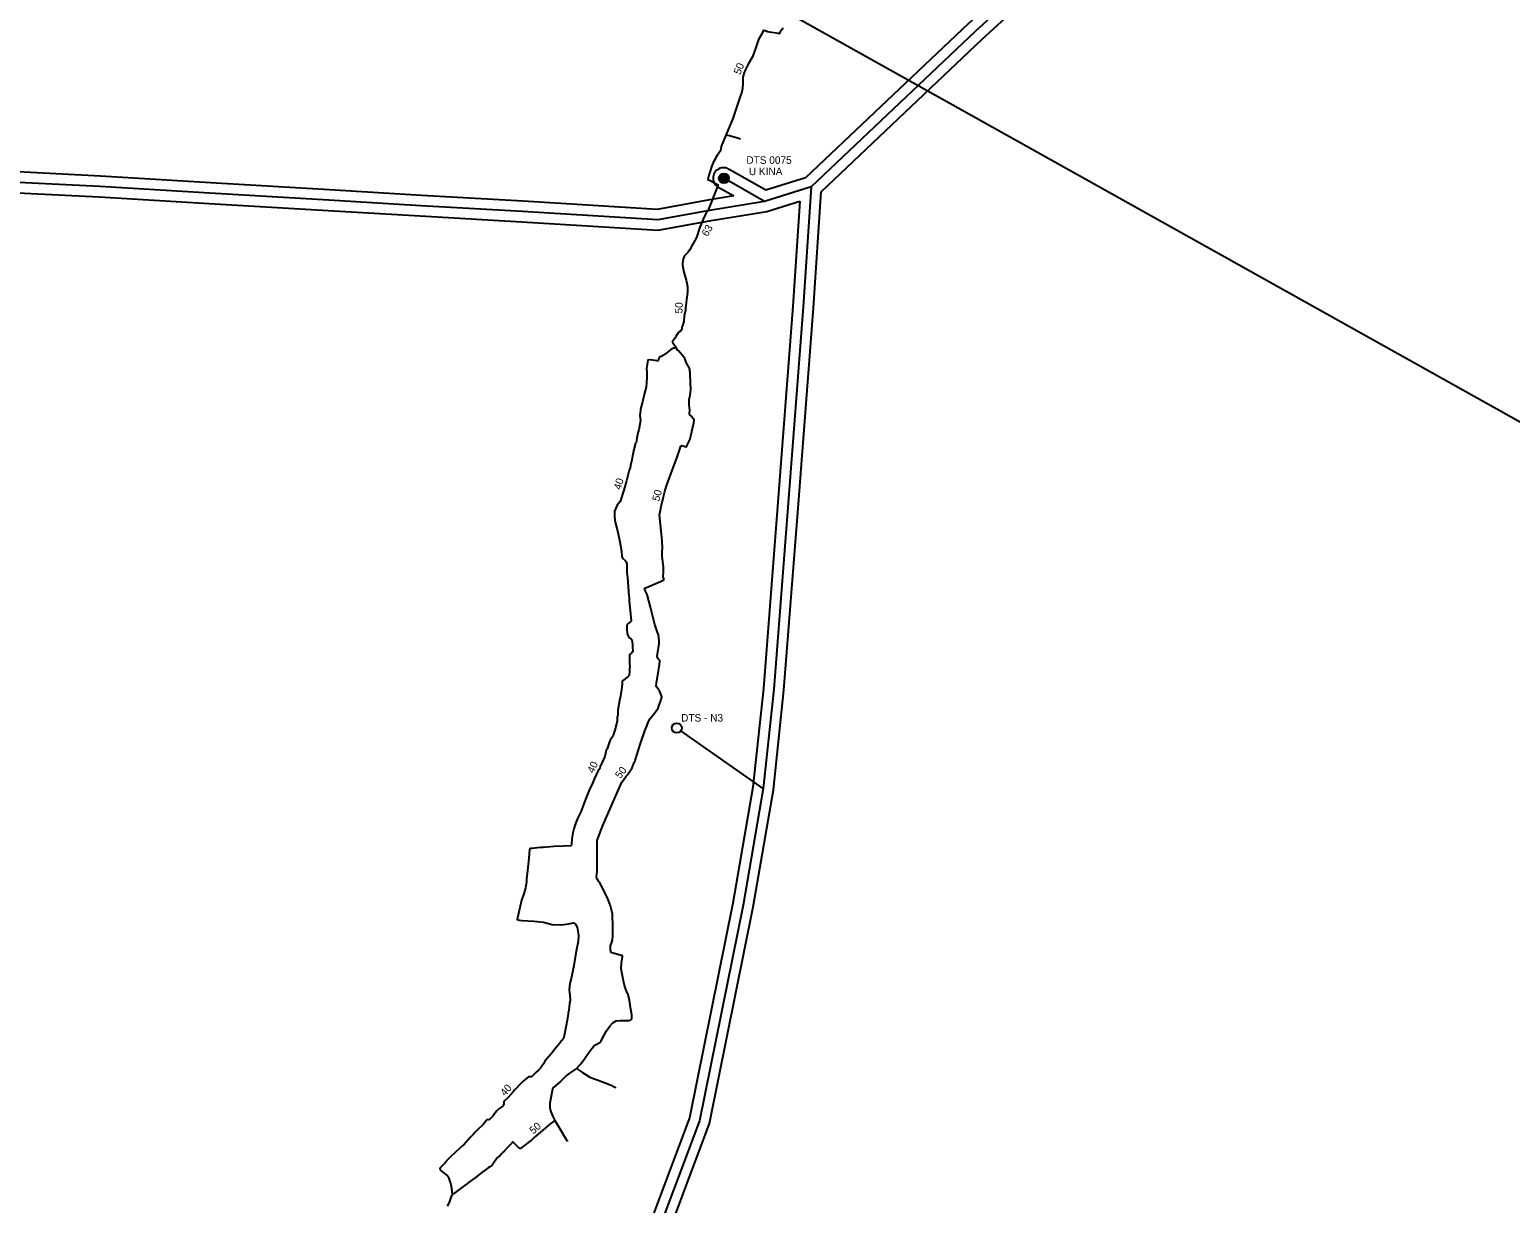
# Model space of a CAD drawing. Extents: x -545241 to -532622, y -1042837 to -1037240.
# Drawn here: x -544227 to -542654, y -1041842 to -1040596 of the extents above; entities that cross this region are included whole.
import ezdxf

# ---------------------------------------------------------------- set-up
doc = ezdxf.new("R2010")
doc.units = 0
for name, color, linetype in [('Vrstva 11', 7, 'Continuous'), ('Vrstva 12', 7, 'Continuous'), ('Vrstva 16', 7, 'Continuous'), ('Vrstva 18', 7, 'Continuous'), ('Vrstva 29', 7, 'Continuous'), ('Vrstva 33', 7, 'Continuous'), ('Vrstva 38', 7, 'Continuous'), ('Vrstva 59', 7, 'Continuous'), ('Vrstva 6', 7, 'Continuous')]:
    doc.layers.add(name, color=color, linetype=linetype)

# ---------------------------------------------------------------- blocks, each defined once
blk = doc.blocks.new('ETRAFN')
at = {"layer": 'Vrstva 6'}
blk.add_circle((0, 0), 7.5, dxfattribs=at)

msp = doc.modelspace()

# ---------------------------------------------------------------- linework, layer by layer
at = {"layer": 'Vrstva 11'}
msp.add_line((-543448.1, -1041401.7), (-543535.6, -1041340.6), dxfattribs=at)
at = {"layer": 'Vrstva 12'}
for radius in [5.25, 4.55, 3.85, 3.15, 2.45, 1.75, 1.05, 0.35]:
    msp.add_circle((-543489.8, -1040753.7), radius, dxfattribs=at)
at = {"layer": 'Vrstva 18'}
for points in [[(-543426.9, -1040594.3), (-543429.9, -1040598), (-543431.1, -1040600.2), (-543431.8, -1040599.9), (-543431.9, -1040600), (-543441.2, -1040598.4), (-543443.1, -1040598.1), (-543443.1, -1040598.1), (-543443.3, -1040597.9), (-543444.6, -1040597.6), (-543445.9, -1040597.2), (-543447.6, -1040596.7), (-543447.8, -1040596.7), (-543448, -1040596.8), (-543448.1, -1040597.2), (-543449.8, -1040600.8), (-543452.9, -1040606.2), (-543455, -1040612.6), (-543456.6, -1040616.9), (-543459.2, -1040624.7), (-543463.8, -1040632.5), (-543466.4, -1040637.5), (-543466.7, -1040638), (-543468.4, -1040642.4), (-543469.6, -1040646.4), (-543469.7, -1040653), (-543470, -1040658.2), (-543471.2, -1040663.4)], [(-543471.2, -1040663.4), (-543472, -1040665.8), (-543480.3, -1040690.3), (-543486.8, -1040705.4), (-543487.8, -1040707.9), (-543492.5, -1040719.9), (-543493.4, -1040724.5), (-543496.8, -1040729.5), (-543498.8, -1040732.4), (-543499.2, -1040733.2), (-543501.2, -1040736.8), (-543502.7, -1040740.5), (-543504.2, -1040746.2), (-543505.9, -1040750.5), (-543506.9, -1040755), (-543504.5, -1040756), (-543504.5, -1040756), (-543497.9, -1040759.5), (-543496.4, -1040760.2), (-543495.8, -1040760.6), (-543506.8, -1040788.1), (-543509.2, -1040791.7), (-543511.6, -1040797.1), (-543514, -1040802.5), (-543515.3, -1040805.6), (-543518.9, -1040816.5), (-543524.3, -1040826.1), (-543526.2, -1040830), (-543528, -1040832.5), (-543531.6, -1040836), (-543532.4, -1040837.4), (-543533.1, -1040839.4), (-543533.8, -1040843.9), (-543533.9, -1040846), (-543532.2, -1040853.5), (-543530, -1040861.9), (-543529.3, -1040865.1), (-543528.5, -1040868.8), (-543528.3, -1040871.6), (-543528.5, -1040873.5), (-543528.8, -1040878), (-543529.4, -1040881.9), (-543529.7, -1040886.1), (-543530.6, -1040891.4), (-543530.7, -1040893.9), (-543531.6, -1040897.7), (-543531.9, -1040900.7), (-543532.2, -1040904.9), (-543532.3, -1040905.8), (-543532.5, -1040906.7), (-543533.8, -1040910.4), (-543534.6, -1040911.8), (-543534.6, -1040912.3), (-543534.4, -1040913.4), (-543534.4, -1040914.3), (-543535.8, -1040915.9), (-543537.6, -1040917), (-543537.6, -1040917), (-543538.5, -1040917.8), (-543540.7, -1040921.6), (-543541.6, -1040923.1), (-543542.3, -1040924.2), (-543543.4, -1040925.6), (-543544.4, -1040926.9), (-543544.6, -1040927.3), (-543544.4, -1040927.8), (-543543.8, -1040928.8), (-543540.5, -1040933.3)], [(-543472.1, -1040712), (-543473.2, -1040711.8), (-543475.2, -1040711.2), (-543481.2, -1040709.2), (-543483.8, -1040708.4), (-543487.8, -1040707.9)], [(-543540.5, -1040933.3), (-543542.1, -1040934.1), (-543543.2, -1040934.1), (-543546.3, -1040936), (-543550.1, -1040938.7), (-543554.7, -1040941.9), (-543556.3, -1040942.8), (-543557.7, -1040943.4), (-543558.6, -1040944.2), (-543559.2, -1040945.8), (-543559.3, -1040946), (-543559.7, -1040947.5), (-543560.7, -1040947.6), (-543568.1, -1040946.3), (-543568.4, -1040946.3), (-543570.4, -1040946.7), (-543571.4, -1040951.4), (-543571.8, -1040955.6), (-543571.6, -1040959.6), (-543571.6, -1040965.6), (-543572.5, -1040975.5), (-543574.6, -1040983.3), (-543576.2, -1040990.9), (-543578.3, -1040999), (-543578.4, -1041000), (-543579, -1041005.7), (-543578.5, -1041011), (-543578.9, -1041014.8), (-543580.2, -1041020.7), (-543580.6, -1041022), (-543580.7, -1041022.9), (-543582.4, -1041029.4), (-543582.5, -1041032), (-543582.6, -1041032.9), (-543582.9, -1041034.1), (-543583.5, -1041035), (-543585.6, -1041041.6), (-543586.6, -1041047.1), (-543587.7, -1041052.8), (-543588.8, -1041058.5), (-543588.9, -1041058.7), (-543589.4, -1041061.1), (-543590.4, -1041063.7), (-543593.3, -1041074.9), (-543596.1, -1041084.7), (-543599.5, -1041096), (-543599.8, -1041096.9), (-543603, -1041100.7), (-543605.9, -1041107.3), (-543605.8, -1041113.6), (-543605.3, -1041118.8), (-543602.8, -1041128), (-543602.3, -1041129.9), (-543601.9, -1041131.3), (-543600.2, -1041139.6), (-543598.7, -1041149.7), (-543598.2, -1041155.3), (-543597.3, -1041157.2), (-543594.4, -1041159.9), (-543593.4, -1041161.1), (-543593, -1041163.5), (-543592.9, -1041172.2), (-543592.2, -1041178), (-543591.4, -1041187.1), (-543591.1, -1041192.3), (-543591.1, -1041193), (-543590.5, -1041199.7), (-543590.4, -1041202.7), (-543589.1, -1041216.1), (-543588.4, -1041223.8), (-543588.8, -1041224.7), (-543589.7, -1041225.3), (-543590.5, -1041225.9), (-543591.5, -1041226.4), (-543592.6, -1041227.6), (-543592.9, -1041228.9), (-543592.7, -1041232.7), (-543592.4, -1041237.1), (-543592.2, -1041238.2), (-543591.5, -1041239.7), (-543590, -1041241.7), (-543588.2, -1041243.2), (-543587.6, -1041243.8), (-543587, -1041248.8), (-543586.8, -1041250.7), (-543586.5, -1041256.4), (-543586.6, -1041256.4), (-543586.7, -1041256.7), (-543588, -1041257.8), (-543589.9, -1041259.4), (-543590.2, -1041259.9), (-543590.2, -1041260.6), (-543590.2, -1041262.4), (-543590.1, -1041262.9), (-543590.1, -1041266.3), (-543590, -1041267), (-543590, -1041269), (-543589.7, -1041272.8), (-543589.7, -1041273.2), (-543589.9, -1041273.7), (-543590.2, -1041277.2)], [(-543558.4, -1041245), (-543559.3, -1041238.6), (-543560.5, -1041234.9), (-543563, -1041227.5), (-543564.7, -1041221.8), (-543567.8, -1041209.2), (-543571.4, -1041195.7), (-543573, -1041192.1), (-543574, -1041189.2), (-543573.3, -1041188.7), (-543572.1, -1041188.3), (-543557.2, -1041181.8), (-543553.7, -1041180.2), (-543553.5, -1041179.5), (-543553.7, -1041178.7), (-543554.3, -1041176.8), (-543553.8, -1041171.2), (-543553.8, -1041170), (-543554, -1041166.2), (-543555, -1041157.6), (-543555.3, -1041154.9), (-543555.5, -1041153.8), (-543555.4, -1041150.9), (-543555.3, -1041150.2), (-543555.3, -1041149.6), (-543554.8, -1041146.8), (-543555.4, -1041138.7), (-543556.1, -1041131.6), (-543558, -1041111.1), (-543556.8, -1041104.2), (-543556.3, -1041102.2), (-543554.2, -1041093.3), (-543552.4, -1041086.3), (-543550.6, -1041080.3), (-543550.6, -1041080.1), (-543549.7, -1041077.4), (-543549, -1041075.3), (-543548, -1041072.5), (-543543.6, -1041061), (-543539, -1041048.7), (-543535.5, -1041038.2), (-543535.3, -1041037.6), (-543534.9, -1041037.5), (-543534.9, -1041037.5), (-543532.1, -1041038.3), (-543532, -1041038.3), (-543531.6, -1041038.4), (-543529.8, -1041038.9), (-543529.2, -1041037.8), (-543525.9, -1041031.4), (-543524.6, -1041025.9), (-543523.1, -1041019.3), (-543521.7, -1041013.4), (-543521.7, -1041013.4), (-543521.7, -1041013), (-543521.4, -1041010.9), (-543521.3, -1041010.3), (-543522.6, -1041008.5), (-543523.6, -1041007.1), (-543523.6, -1041007), (-543526.3, -1041004.5), (-543526.3, -1041003.9), (-543526, -1041000), (-543526, -1041000), (-543526.6, -1040994.3), (-543526.6, -1040993.5), (-543526.6, -1040988.4), (-543525.7, -1040983.8), (-543525.1, -1040981.2), (-543524.9, -1040978.3), (-543525.1, -1040970.1), (-543525.7, -1040962), (-543525.7, -1040961.8), (-543525.7, -1040959.7), (-543525.8, -1040958.7), (-543525.8, -1040956.6), (-543527.1, -1040953.9), (-543527.8, -1040953.2), (-543528.9, -1040951.1), (-543529.1, -1040950.8), (-543530.8, -1040946.2), (-543531.4, -1040945.2), (-543532, -1040943.9), (-543537.9, -1040936.9), (-543538.2, -1040936.6), (-543539.1, -1040936.2), (-543539.5, -1040936.1), (-543539.7, -1040935.7), (-543539.9, -1040934.5), (-543540.2, -1040933.7), (-543540.5, -1040933.3)], [(-543646.3, -1041699.1), (-543644.2, -1041696.9), (-543644.1, -1041696.6), (-543642.5, -1041694.7), (-543638.6, -1041689.9), (-543633.1, -1041682), (-543630.1, -1041677.8), (-543628, -1041675.2), (-543626.2, -1041674), (-543621.7, -1041671.5), (-543620.2, -1041669.7), (-543616.5, -1041663), (-543614.3, -1041659.1), (-543612.7, -1041656.5), (-543612.6, -1041656.4), (-543611, -1041654.2), (-543607.7, -1041650.4), (-543604.2, -1041648.5), (-543599.7, -1041647.9), (-543590.9, -1041648.2), (-543589.1, -1041647.6), (-543587.7, -1041646.2), (-543587.4, -1041644.6), (-543587.7, -1041642), (-543589, -1041634.3), (-543589.8, -1041628.8), (-543590.4, -1041625.2), (-543591.6, -1041620.4), (-543592.1, -1041619.2), (-543594.3, -1041614.1), (-543595.8, -1041609.5), (-543597.5, -1041600.7), (-543598.8, -1041593.3), (-543598.6, -1041587), (-543597.3, -1041580.6), (-543597.4, -1041579.7), (-543597.6, -1041579.5), (-543608.7, -1041576.1), (-543609.5, -1041575.8), (-543609.9, -1041575.3), (-543610.3, -1041571.7), (-543610.3, -1041569.6), (-543610.1, -1041568.7), (-543608.8, -1041564.9), (-543608.1, -1041562.3), (-543607.8, -1041558), (-543607.7, -1041551), (-543607.7, -1041548.4), (-543608, -1041535), (-543608.3, -1041533.4), (-543610.2, -1041526.2), (-543613.4, -1041517.9), (-543622, -1041501.3), (-543622.9, -1041500), (-543624.8, -1041497.2), (-543625.2, -1041495), (-543624.3, -1041490), (-543624.3, -1041475.7), (-543624.5, -1041457.7), (-543624.4, -1041457), (-543620.9, -1041447.3), (-543618.2, -1041441), (-543602.5, -1041404.5), (-543598.2, -1041395.1), (-543598.2, -1041395.1), (-543597.9, -1041394.5), (-543593.5, -1041388.6), (-543592, -1041387.3), (-543591, -1041386.2), (-543590.9, -1041385.2), (-543590.7, -1041384.9), (-543587.1, -1041379.6), (-543584.9, -1041374.2), (-543584.4, -1041373.5), (-543584.1, -1041371.8), (-543578.7, -1041354.9), (-543573.8, -1041340.4), (-543571.1, -1041334.5), (-543569.8, -1041330.5), (-543567.9, -1041327.5), (-543563.4, -1041321.5), (-543559.7, -1041316.5), (-543557.7, -1041311), (-543557.5, -1041310.2), (-543556, -1041306), (-543555.7, -1041304.2), (-543557, -1041300.4), (-543558.2, -1041298), (-543561.5, -1041293.7), (-543561.7, -1041292.8), (-543561.3, -1041289.7), (-543560.1, -1041281.1), (-543558.6, -1041272.5), (-543557.7, -1041267), (-543557.8, -1041265.8), (-543559.5, -1041263.8), (-543560.8, -1041261.5), (-543560, -1041256.4), (-543558.7, -1041250.2), (-543558.4, -1041247.6), (-543558.4, -1041245)], [(-543590.2, -1041277.2), (-543590.4, -1041281.5), (-543590.7, -1041281.9), (-543591.4, -1041282.9), (-543597.3, -1041287.5), (-543597.7, -1041288.1), (-543597.9, -1041290.2), (-543597.8, -1041291.7), (-543598.2, -1041293.3), (-543598.2, -1041293.9), (-543599.5, -1041303.5), (-543600.5, -1041308.3), (-543600.4, -1041308.5), (-543600.5, -1041308.6), (-543601.3, -1041312.3), (-543602.5, -1041318.5), (-543602.5, -1041320.8), (-543602.6, -1041323.5), (-543603.1, -1041326.6), (-543603.2, -1041328.9), (-543603.2, -1041330.3), (-543605.6, -1041339.9), (-543606.9, -1041344.1), (-543607.4, -1041345.8), (-543610.6, -1041350.5), (-543611, -1041351), (-543613.9, -1041359.6), (-543614.4, -1041360.4), (-543614.8, -1041361), (-543615.3, -1041362.8), (-543615.3, -1041362.8), (-543615.6, -1041364.4), (-543616.4, -1041367.7), (-543621.2, -1041378.2), (-543621.7, -1041380.3), (-543622.5, -1041381.1), (-543625.5, -1041387.2), (-543627.4, -1041391.6), (-543629, -1041395.4), (-543632.4, -1041402.9), (-543637.2, -1041414.1), (-543639.7, -1041420.7), (-543641.8, -1041426.5), (-543642.9, -1041428.5), (-543644.8, -1041432.8), (-543647.3, -1041439), (-543647.4, -1041439.2), (-543648.1, -1041441.1), (-543648.5, -1041442.2), (-543648.6, -1041442.4), (-543648.7, -1041443.3), (-543649.1, -1041444.5), (-543650.2, -1041448.6), (-543651.2, -1041455.1), (-543651.6, -1041460.8), (-543652.1, -1041462.7), (-543660.4, -1041463), (-543670.1, -1041463.3), (-543681.6, -1041464.2), (-543684.6, -1041464.3), (-543693.8, -1041465.3), (-543694.8, -1041465.4), (-543695.8, -1041465.9), (-543696.2, -1041466.6), (-543697.1, -1041475.8), (-543697.9, -1041485.5), (-543699.3, -1041498), (-543699.5, -1041500), (-543699.8, -1041503.3), (-543700.5, -1041507.2), (-543702.3, -1041513.4), (-543704.6, -1041520.2), (-543708.8, -1041537.5), (-543709.1, -1041539), (-543709.2, -1041540.7), (-543706.8, -1041541.5), (-543703.9, -1041541.8), (-543691.6, -1041542.6), (-543681.3, -1041543.5), (-543672.2, -1041546.1), (-543662.4, -1041546.3), (-543654.7, -1041545.5), (-543649.7, -1041544.5), (-543647.5, -1041545.8), (-543645.6, -1041549.1), (-543644.2, -1041557.5), (-543644.6, -1041564.3), (-543646.6, -1041574.3), (-543649.3, -1041589.7), (-543649.4, -1041591.3), (-543651.8, -1041602.2), (-543653.1, -1041607.5), (-543653.6, -1041611.3), (-543654.2, -1041615.9), (-543653.4, -1041621), (-543653.4, -1041621.2), (-543653.2, -1041626), (-543653.2, -1041626.5), (-543653.2, -1041626.7), (-543653.6, -1041629.9), (-543654.6, -1041637)], [(-543654.6, -1041637), (-543655.1, -1041639.9), (-543655.1, -1041639.9), (-543655.2, -1041641.1), (-543656.2, -1041647.7), (-543657.8, -1041655.2), (-543659.5, -1041664.2), (-543660.1, -1041667.2), (-543660.9, -1041668), (-543661.6, -1041668.9), (-543662.2, -1041669.6), (-543663.4, -1041671.2), (-543664, -1041671.9), (-543664, -1041672), (-543665.9, -1041674.4), (-543670.8, -1041680.3), (-543672.7, -1041682.7), (-543673.3, -1041683.5), (-543673.3, -1041683.5), (-543680, -1041691.4), (-543681.5, -1041694.1), (-543684, -1041697.5), (-543684.7, -1041698.7), (-543685.8, -1041699.8), (-543686.7, -1041700.7), (-543689.5, -1041703.3), (-543694.2, -1041707.7), (-543695.1, -1041708), (-543696.8, -1041707.7), (-543697.4, -1041707.7), (-543699.2, -1041709.2), (-543703, -1041712.5), (-543704.4, -1041713.9), (-543705.1, -1041714.5), (-543712.2, -1041722.2), (-543713.6, -1041723.7), (-543718.9, -1041729.7), (-543719.1, -1041729.8), (-543723.5, -1041733.9), (-543723.6, -1041734), (-543723.6, -1041734.4), (-543723.5, -1041734.9), (-543723.4, -1041735.6), (-543723.4, -1041736.4), (-543724.4, -1041738.4), (-543724.7, -1041738.9), (-543727.9, -1041741.2), (-543728.7, -1041741.9), (-543729.4, -1041742.6), (-543731.3, -1041744.5), (-543735.3, -1041749.7), (-543738.3, -1041752.7), (-543738.9, -1041753.2), (-543739.6, -1041753.4), (-543741.1, -1041753.2), (-543741.7, -1041753.7), (-543742.2, -1041754.3), (-543742.6, -1041754.9), (-543745.6, -1041758.6), (-543745.8, -1041758.8), (-543746.8, -1041759.8), (-543750, -1041762.9), (-543752.4, -1041765.2), (-543754.1, -1041766.7), (-543755.9, -1041768.7), (-543759.2, -1041772.2), (-543766, -1041780.2), (-543767, -1041780.8), (-543774.5, -1041787.5), (-543774.6, -1041787.5), (-543775.2, -1041788.2), (-543775.8, -1041788.8), (-543779.8, -1041792.5), (-543781.1, -1041793.8), (-543782.3, -1041795), (-543783, -1041795.7), (-543785.7, -1041798.7), (-543786, -1041799.2), (-543790.9, -1041804.2), (-543791.3, -1041804.6), (-543791.5, -1041805.3), (-543791, -1041806.5), (-543789.8, -1041808.1), (-543783.7, -1041812.8), (-543783.5, -1041813), (-543783.4, -1041813.1), (-543783.1, -1041813.6), (-543782.6, -1041814.4), (-543782.4, -1041814.7), (-543780.4, -1041820.1), (-543780.3, -1041820.5), (-543779.2, -1041826.1), (-543778.8, -1041830), (-543778.3, -1041831.6), (-543777.8, -1041832.6)], [(-543646.3, -1041699.1), (-543655.3, -1041704.9), (-543657.2, -1041706.9), (-543663.3, -1041712.8), (-543670.3, -1041718.9), (-543671.8, -1041720.5), (-543672.3, -1041722.6), (-543674.8, -1041735.9), (-543674.6, -1041740.3), (-543673.8, -1041743.9), (-543671.9, -1041749.3), (-543669.4, -1041754.3), (-543674.6, -1041758), (-543679.8, -1041762.5), (-543684.6, -1041766.7), (-543691, -1041772.1), (-543694, -1041775.1), (-543696.5, -1041777), (-543705.9, -1041784), (-543706.7, -1041784), (-543707.4, -1041783.7), (-543711.2, -1041779.9), (-543713.9, -1041777), (-543714.1, -1041777.2), (-543714.3, -1041777.5), (-543714.9, -1041778.1), (-543715.2, -1041778.3), (-543718.9, -1041782.3), (-543719.7, -1041782.8), (-543723.3, -1041786.9), (-543723.7, -1041787.4), (-543724.3, -1041788), (-543726.7, -1041790.5), (-543727.6, -1041791.3), (-543728.7, -1041792.5), (-543730.6, -1041794), (-543736, -1041801.8), (-543736.3, -1041802.2), (-543736.3, -1041802.2), (-543738.5, -1041803.5), (-543740.1, -1041804.4), (-543744.7, -1041807.9), (-543745.5, -1041808.5), (-543750, -1041811.9), (-543752.2, -1041813.6), (-543761.4, -1041820.5), (-543762.2, -1041821.1), (-543765.6, -1041823.6), (-543776.9, -1041832), (-543777.8, -1041832.6)], [(-543646.3, -1041699.1), (-543640.1, -1041703.2), (-543632.1, -1041708.1), (-543620.4, -1041712.6), (-543609.6, -1041716.7), (-543605.6, -1041718.7), (-543604.5, -1041719.7)], [(-543669.4, -1041754.3), (-543667.7, -1041757), (-543661.3, -1041767.6), (-543661.1, -1041767.9), (-543657.1, -1041774.8), (-543656.4, -1041775.7), (-543656, -1041776.5)], [(-543783.3, -1041845.3), (-543781.4, -1041841.2), (-543779.8, -1041836.9), (-543778.4, -1041833), (-543777.8, -1041832.6)]]:
    msp.add_lwpolyline(points, dxfattribs=at)
at = {"layer": 'Vrstva 33'}
for p, q in [((-543445.3, -1040766.3), (-543483.3, -1040744.7)), ((-543494.3, -1040763.8), (-543479.1, -1040772.4))]:
    msp.add_line(p, q, dxfattribs=at)
for points in [[(-542699.6, -1040093), (-542837.1, -1040220.9), (-542920.5, -1040299.7), (-543059.3, -1040431.4), (-543149.1, -1040515.5), (-543230.4, -1040589.7), (-543402.9, -1040753.1), (-543445.3, -1040766.3)], [(-543386.5, -1040767.9), (-543215.4, -1040605.8), (-543134.2, -1040531.6)], [(-543479.1, -1040772.4), (-543506.8, -1040776.9), (-543560.8, -1040786.8), (-543703.1, -1040778), (-543811, -1040771.8), (-543908.7, -1040765.9), (-544035.2, -1040758.6), (-544152.1, -1040751.4), (-544260.8, -1040745.9), (-544428.8, -1040736.2)], [(-544443.9, -1040760.4), (-544431.3, -1040758.1), (-544262, -1040767.9), (-544153.3, -1040773.3), (-544036.5, -1040780.6), (-543910, -1040787.9), (-543812.3, -1040793.7), (-543704.5, -1040800), (-543559.5, -1040808.9), (-543503.1, -1040798.6), (-543444, -1040789), (-543409.2, -1040778.1)], [(-543409.2, -1040778.1), (-543416.5, -1040889.5), (-543432.7, -1041102.2), (-543447.8, -1041295.3), (-543459, -1041400.2), (-543480.1, -1041523.4), (-543526.2, -1041751.4), (-543580.5, -1041895.8), (-543620.9, -1041996.2)], [(-543601.3, -1042006.5), (-543560, -1041903.8), (-543505, -1041757.5), (-543458.5, -1041527.4), (-543437.2, -1041403.2), (-543425.9, -1041297.3), (-543410.7, -1041103.9), (-543394.5, -1040891.1), (-543386.5, -1040767.9)]]:
    msp.add_lwpolyline(points, dxfattribs=at)
msp.add_arc((-543490.1, -1040753.5), 11.1, 52.4421, 247.8227, dxfattribs=at)
at = {"layer": 'Vrstva 38'}
msp.add_line((-543446.5, -1040778.2), (-543489.8, -1040753.7), dxfattribs=at)
for points in [[(-543141.7, -1040523.6), (-543222.9, -1040597.8), (-543397.2, -1040762.8), (-543446.5, -1040778.2), (-543505, -1040787.8), (-543560.1, -1040797.8), (-543703.8, -1040789), (-543811.6, -1040782.8), (-543909.3, -1040776.9), (-544035.9, -1040769.6), (-544152.7, -1040762.3), (-544261.4, -1040756.9), (-544432, -1040747), (-544512.3, -1040761.5)], [(-543397.2, -1040762.8), (-543405.5, -1040890.3), (-543421.7, -1041103), (-543436.8, -1041296.3), (-543448.1, -1041401.7), (-543469.3, -1041525.4), (-543515.6, -1041754.5), (-543570.3, -1041899.8), (-543614.7, -1042010.4), (-543643.3, -1042081.7), (-543619.2, -1042247.4), (-543599.2, -1042381.3), (-543591.1, -1042442.1), (-543575, -1042577.5)]]:
    msp.add_lwpolyline(points, dxfattribs=at)
at = {"layer": 'Vrstva 59'}
msp.add_lwpolyline([(-545240.6, -1039561.7), (-540702.1, -1042097)], dxfattribs=at)

# ---------------------------------------------------------------- block references
at = {"layer": 'Vrstva 29', "xscale": 0.7, "yscale": 0.7}
msp.add_blockref('ETRAFN', (-543539.8, -1041337.4), dxfattribs=at)

# ---------------------------------------------------------------- texts
at = {"layer": 'Vrstva 16'}
for s, rotation, p in [('50', 68.0864, (-543472.4, -1040644.2)), ('63', 59.3728, (-543507.2, -1040816.2)), ('50', 87.4603, (-543533.9, -1040897.4)), ('40', 74.2795, (-543599.3, -1041084.9)), ('50', 75.1041, (-543558.4, -1041097.2)), ('40', 63.9669, (-543628.3, -1041386.1)), ('50', 53.1145, (-543599.7, -1041391.8)), ('40', 48.3925, (-543722.3, -1041729)), ('50', 40.6161, (-543692.2, -1041769.2))]:
    msp.add_text(s, height=8, rotation=rotation, dxfattribs=at).set_placement(p)
at = {"layer": 'Vrstva 59'}
for s, p in [('DTS 0075', (-543465.9, -1040738.3)), ('U KINA', (-543463.2, -1040750.3)), ('DTS - N3', (-543535.2, -1041330.6))]:
    msp.add_text(s, height=8, dxfattribs=at).set_placement(p)

doc.saveas('drawing.dxf')
